(* Logix 5000 project; controller Test vendor 1 type 14 code 92 rev 33.11; software revision 33.00; part 2 of 2 *)

ADD_ON_INSTRUCTION Banner_QM30VT3_PD_FP_RMS_v5   (* revision 1.0 *)
VAR_IN_OUT
   Bytes : SINT[32]; {required}
   Data : Banner_QM30VT3_FP_RMS_PD_v5; {required}
END_VAR
VAR
   Temp : DINT[16]; {access None}
END_VAR

ROUTINE Logic   (* ladder *)
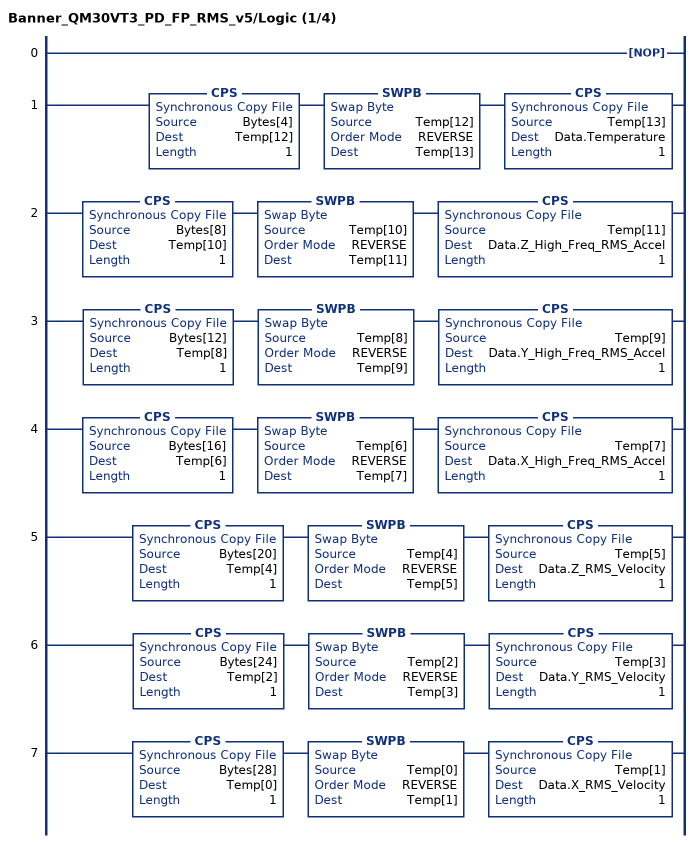
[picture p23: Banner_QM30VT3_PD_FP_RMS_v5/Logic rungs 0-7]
   0: NOP();
   1: CPS(Bytes[4],Temp[12],1)SWPB(Temp[12],REVERSE,Temp[13])CPS(Temp[13],Data.Temperature,1);
   2: CPS(Bytes[8],Temp[10],1)SWPB(Temp[10],REVERSE,Temp[11])CPS(Temp[11],Data.Z_High_Freq_RMS_Accel,1);
   3: CPS(Bytes[12],Temp[8],1)SWPB(Temp[8],REVERSE,Temp[9])CPS(Temp[9],Data.Y_High_Freq_RMS_Accel,1);
   4: CPS(Bytes[16],Temp[6],1)SWPB(Temp[6],REVERSE,Temp[7])CPS(Temp[7],Data.X_High_Freq_RMS_Accel,1);
   5: CPS(Bytes[20],Temp[4],1)SWPB(Temp[4],REVERSE,Temp[5])CPS(Temp[5],Data.Z_RMS_Velocity,1);
   6: CPS(Bytes[24],Temp[2],1)SWPB(Temp[2],REVERSE,Temp[3])CPS(Temp[3],Data.Y_RMS_Velocity,1);
   7: CPS(Bytes[28],Temp[0],1)SWPB(Temp[0],REVERSE,Temp[1])CPS(Temp[1],Data.X_RMS_Velocity,1);
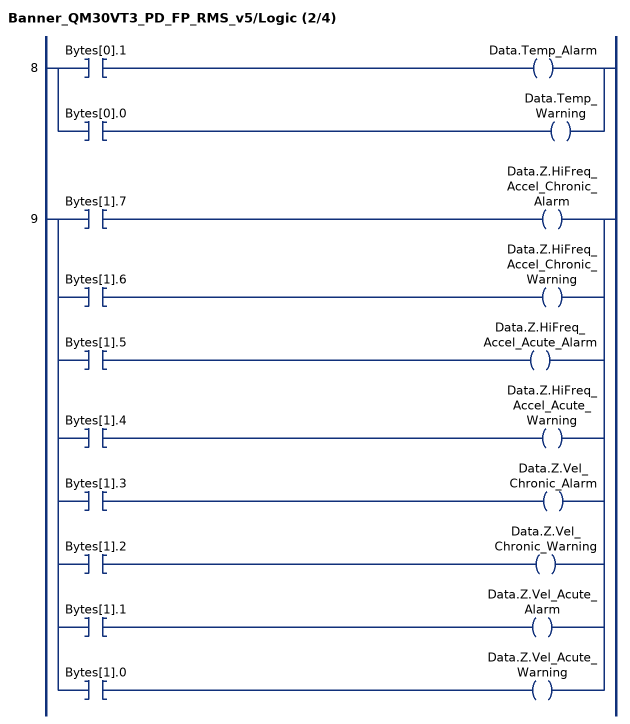
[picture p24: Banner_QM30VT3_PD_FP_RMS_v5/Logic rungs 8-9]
   8: [XIC(Bytes[0].1) OTE(Data.Temp_Alarm) ,XIC(Bytes[0].0) OTE(Data.Temp_Warning) ];
   9: [XIC(Bytes[1].7) OTE(Data.Z.HiFreq_Accel_Chronic_Alarm) ,XIC(Bytes[1].6) OTE(Data.Z.HiFreq_Accel_Chronic_Warning) ,XIC(Bytes[1].5) OTE(Data.Z.HiFreq_Accel_Acute_Alarm) ,XIC(Bytes[1].4) OTE(Data.Z.HiFreq_Accel_Acute_Warning) ,XIC(Bytes[1].3) OTE(Data.Z.Vel_Chronic_Alarm) ,XIC(Bytes[1].2) OTE(Data.Z.Vel_Chronic_Warning) ,XIC(Bytes[1].1) OTE(Data.Z.Vel_Acute_Alarm) ,XIC(Bytes[1].0) OTE(Data.Z.Vel_Acute_Warning) ];
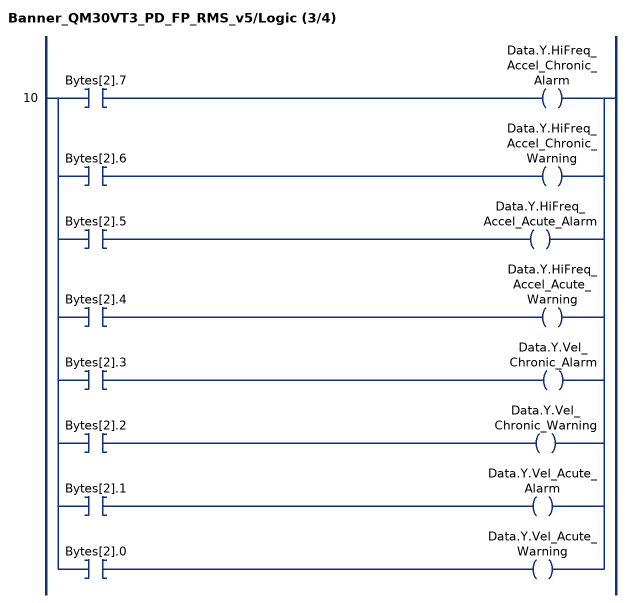
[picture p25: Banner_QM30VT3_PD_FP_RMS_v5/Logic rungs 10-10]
   10: [XIC(Bytes[2].7) OTE(Data.Y.HiFreq_Accel_Chronic_Alarm) ,XIC(Bytes[2].6) OTE(Data.Y.HiFreq_Accel_Chronic_Warning) ,XIC(Bytes[2].5) OTE(Data.Y.HiFreq_Accel_Acute_Alarm) ,XIC(Bytes[2].4) OTE(Data.Y.HiFreq_Accel_Acute_Warning) ,XIC(Bytes[2].3) OTE(Data.Y.Vel_Chronic_Alarm) ,XIC(Bytes[2].2) OTE(Data.Y.Vel_Chronic_Warning) ,XIC(Bytes[2].1) OTE(Data.Y.Vel_Acute_Alarm) ,XIC(Bytes[2].0) OTE(Data.Y.Vel_Acute_Warning) ];
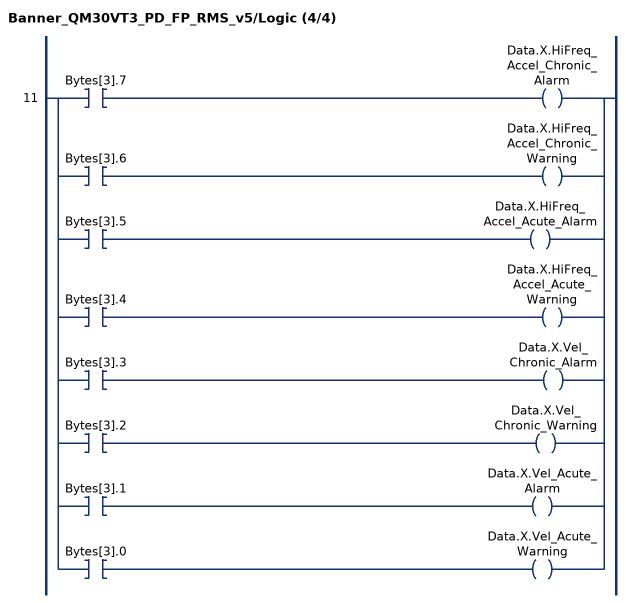
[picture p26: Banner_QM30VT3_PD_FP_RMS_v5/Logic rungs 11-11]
   11: [XIC(Bytes[3].7) OTE(Data.X.HiFreq_Accel_Chronic_Alarm) ,XIC(Bytes[3].6) OTE(Data.X.HiFreq_Accel_Chronic_Warning) ,XIC(Bytes[3].5) OTE(Data.X.HiFreq_Accel_Acute_Alarm) ,XIC(Bytes[3].4) OTE(Data.X.HiFreq_Accel_Acute_Warning) ,XIC(Bytes[3].3) OTE(Data.X.Vel_Chronic_Alarm) ,XIC(Bytes[3].2) OTE(Data.X.Vel_Chronic_Warning) ,XIC(Bytes[3].1) OTE(Data.X.Vel_Acute_Alarm) ,XIC(Bytes[3].0) OTE(Data.X.Vel_Acute_Warning) ];
END_ROUTINE
END_ADD_ON_INSTRUCTION

ADD_ON_INSTRUCTION Banner_QM30VT3_PD_SS_RMS_v5   (* revision 1.0 *)
VAR_IN_OUT
   Bytes : SINT[32]; {required}
   Data : Banner_QM30VT3_SS_RMS_PD_v5; {required}
END_VAR
VAR
   Temp : DINT[16]; {access None}
END_VAR

ROUTINE Logic   (* ladder *)
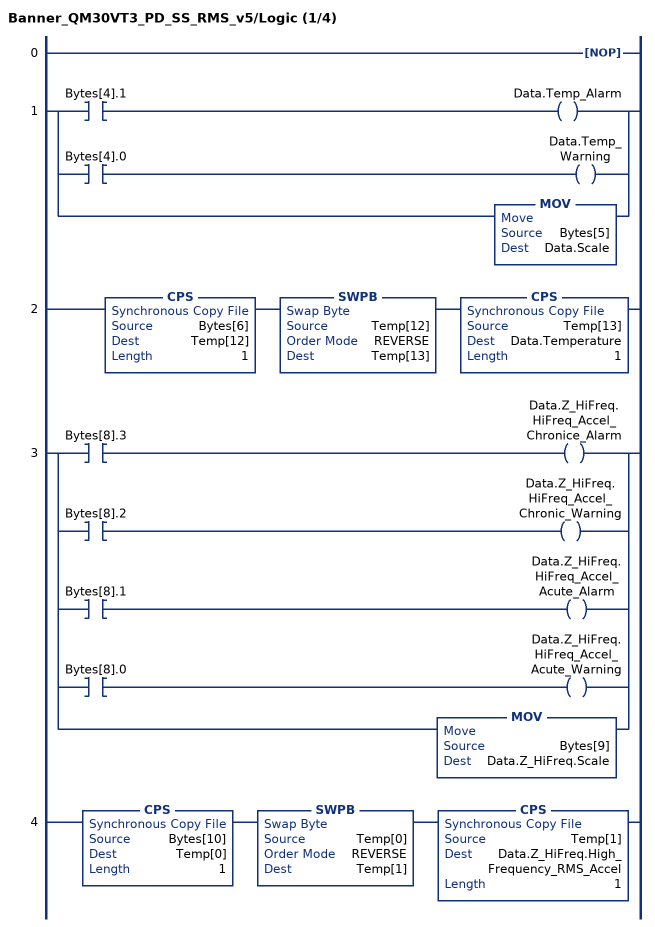
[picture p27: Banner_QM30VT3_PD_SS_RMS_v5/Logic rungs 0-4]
   0: NOP();
   1: [XIC(Bytes[4].1) OTE(Data.Temp_Alarm) ,XIC(Bytes[4].0) OTE(Data.Temp_Warning) ,MOV(Bytes[5],Data.Scale) ];
   2: CPS(Bytes[6],Temp[12],1)SWPB(Temp[12],REVERSE,Temp[13])CPS(Temp[13],Data.Temperature,1);
   3: [XIC(Bytes[8].3) OTE(Data.Z_HiFreq.HiFreq_Accel_Chronice_Alarm) ,XIC(Bytes[8].2) OTE(Data.Z_HiFreq.HiFreq_Accel_Chronic_Warning) ,XIC(Bytes[8].1) OTE(Data.Z_HiFreq.HiFreq_Accel_Acute_Alarm) ,XIC(Bytes[8].0) OTE(Data.Z_HiFreq.HiFreq_Accel_Acute_Warning) ,MOV(Bytes[9],Data.Z_HiFreq.Scale) ];
   4: CPS(Bytes[10],Temp[0],1)SWPB(Temp[0],REVERSE,Temp[1])CPS(Temp[1],Data.Z_HiFreq.High_Frequency_RMS_Accel,1);
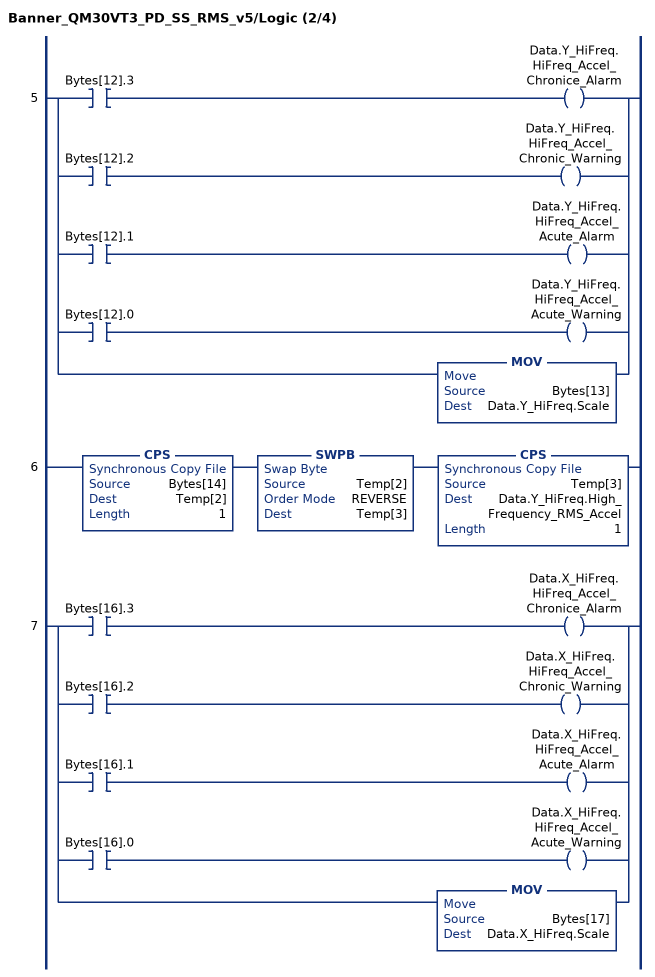
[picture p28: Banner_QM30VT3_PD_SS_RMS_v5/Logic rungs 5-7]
   5: [XIC(Bytes[12].3) OTE(Data.Y_HiFreq.HiFreq_Accel_Chronice_Alarm) ,XIC(Bytes[12].2) OTE(Data.Y_HiFreq.HiFreq_Accel_Chronic_Warning) ,XIC(Bytes[12].1) OTE(Data.Y_HiFreq.HiFreq_Accel_Acute_Alarm) ,XIC(Bytes[12].0) OTE(Data.Y_HiFreq.HiFreq_Accel_Acute_Warning) ,MOV(Bytes[13],Data.Y_HiFreq.Scale) ];
   6: CPS(Bytes[14],Temp[2],1)SWPB(Temp[2],REVERSE,Temp[3])CPS(Temp[3],Data.Y_HiFreq.High_Frequency_RMS_Accel,1);
   7: [XIC(Bytes[16].3) OTE(Data.X_HiFreq.HiFreq_Accel_Chronice_Alarm) ,XIC(Bytes[16].2) OTE(Data.X_HiFreq.HiFreq_Accel_Chronic_Warning) ,XIC(Bytes[16].1) OTE(Data.X_HiFreq.HiFreq_Accel_Acute_Alarm) ,XIC(Bytes[16].0) OTE(Data.X_HiFreq.HiFreq_Accel_Acute_Warning) ,MOV(Bytes[17],Data.X_HiFreq.Scale) ];
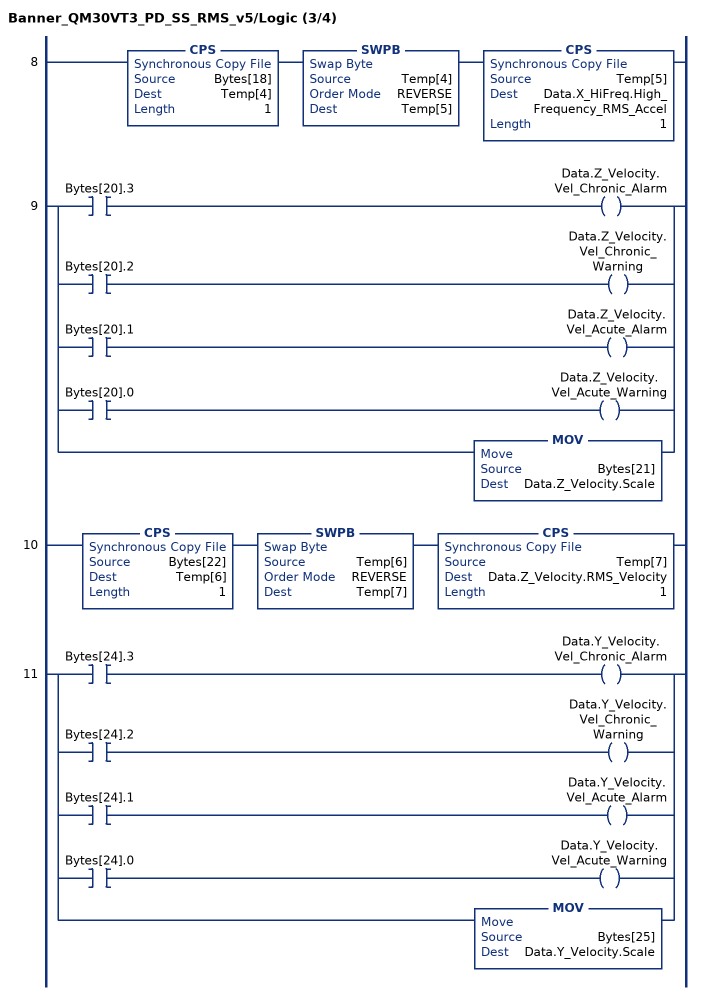
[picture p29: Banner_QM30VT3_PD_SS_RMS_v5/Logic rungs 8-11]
   8: CPS(Bytes[18],Temp[4],1)SWPB(Temp[4],REVERSE,Temp[5])CPS(Temp[5],Data.X_HiFreq.High_Frequency_RMS_Accel,1);
   9: [XIC(Bytes[20].3) OTE(Data.Z_Velocity.Vel_Chronic_Alarm) ,XIC(Bytes[20].2) OTE(Data.Z_Velocity.Vel_Chronic_Warning) ,XIC(Bytes[20].1) OTE(Data.Z_Velocity.Vel_Acute_Alarm) ,XIC(Bytes[20].0) OTE(Data.Z_Velocity.Vel_Acute_Warning) ,MOV(Bytes[21],Data.Z_Velocity.Scale) ];
   10: CPS(Bytes[22],Temp[6],1)SWPB(Temp[6],REVERSE,Temp[7])CPS(Temp[7],Data.Z_Velocity.RMS_Velocity,1);
   11: [XIC(Bytes[24].3) OTE(Data.Y_Velocity.Vel_Chronic_Alarm) ,XIC(Bytes[24].2) OTE(Data.Y_Velocity.Vel_Chronic_Warning) ,XIC(Bytes[24].1) OTE(Data.Y_Velocity.Vel_Acute_Alarm) ,XIC(Bytes[24].0) OTE(Data.Y_Velocity.Vel_Acute_Warning) ,MOV(Bytes[25],Data.Y_Velocity.Scale) ];
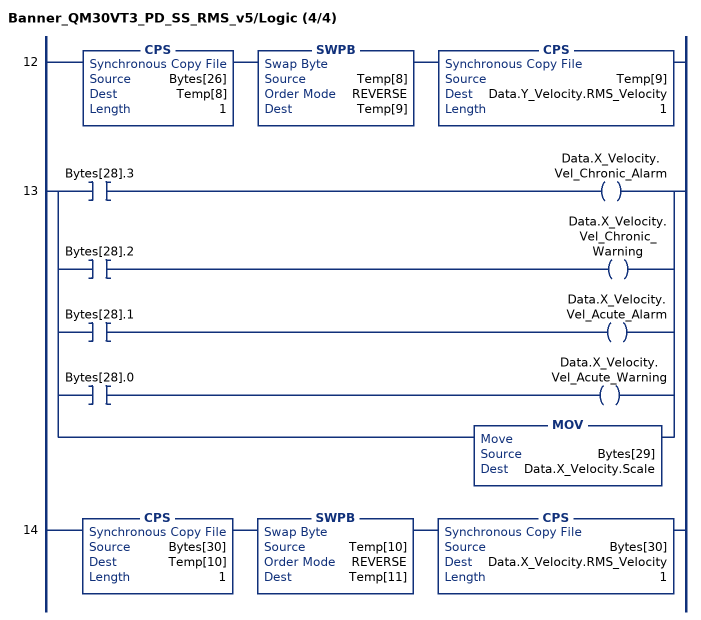
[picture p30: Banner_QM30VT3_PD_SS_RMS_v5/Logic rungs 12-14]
   12: CPS(Bytes[26],Temp[8],1)SWPB(Temp[8],REVERSE,Temp[9])CPS(Temp[9],Data.Y_Velocity.RMS_Velocity,1);
   13: [XIC(Bytes[28].3) OTE(Data.X_Velocity.Vel_Chronic_Alarm) ,XIC(Bytes[28].2) OTE(Data.X_Velocity.Vel_Chronic_Warning) ,XIC(Bytes[28].1) OTE(Data.X_Velocity.Vel_Acute_Alarm) ,XIC(Bytes[28].0) OTE(Data.X_Velocity.Vel_Acute_Warning) ,MOV(Bytes[29],Data.X_Velocity.Scale) ];
   14: CPS(Bytes[30],Temp[10],1)SWPB(Temp[10],REVERSE,Temp[11])CPS(Bytes[30],Data.X_Velocity.RMS_Velocity,1);
END_ROUTINE
END_ADD_ON_INSTRUCTION

ADD_ON_INSTRUCTION Banner_QM30VT3_PD_User_v5   (* revision 1.0 *)
VAR_IN_OUT
   Bytes : SINT[32]; {required}
   Data : Banner_QM30VT3_User_PD_v5; {required}
END_VAR
VAR
   Temp : DINT[16]; {access None}
END_VAR

ROUTINE Logic   (* ladder *)
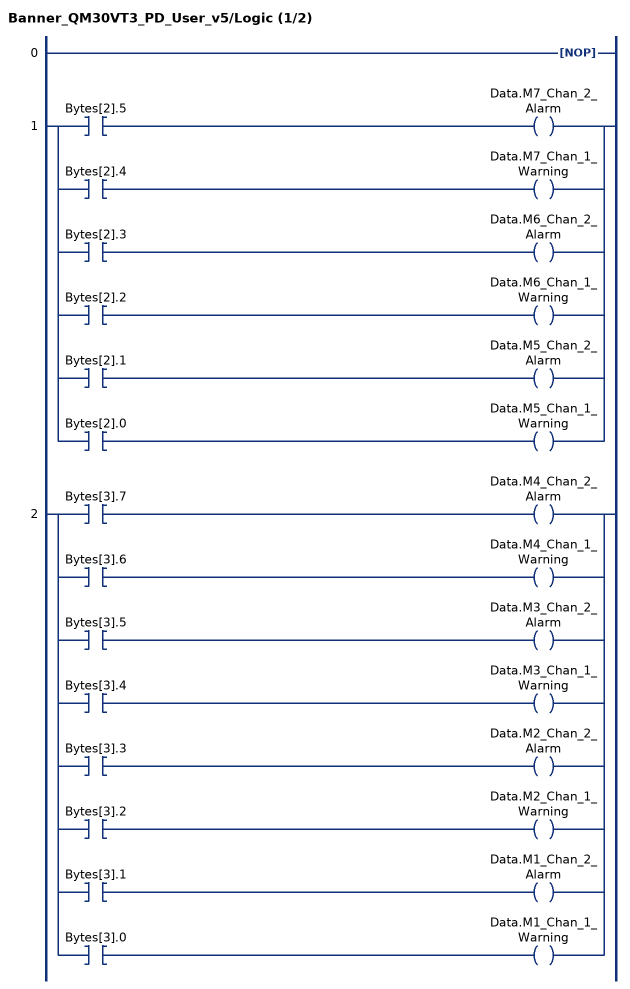
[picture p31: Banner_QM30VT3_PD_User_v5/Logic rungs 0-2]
   0: NOP();
   1: [XIC(Bytes[2].5) OTE(Data.M7_Chan_2_Alarm) ,XIC(Bytes[2].4) OTE(Data.M7_Chan_1_Warning) ,XIC(Bytes[2].3) OTE(Data.M6_Chan_2_Alarm) ,XIC(Bytes[2].2) OTE(Data.M6_Chan_1_Warning) ,XIC(Bytes[2].1) OTE(Data.M5_Chan_2_Alarm) ,XIC(Bytes[2].0) OTE(Data.M5_Chan_1_Warning) ];
   2: [XIC(Bytes[3].7) OTE(Data.M4_Chan_2_Alarm) ,XIC(Bytes[3].6) OTE(Data.M4_Chan_1_Warning) ,XIC(Bytes[3].5) OTE(Data.M3_Chan_2_Alarm) ,XIC(Bytes[3].4) OTE(Data.M3_Chan_1_Warning) ,XIC(Bytes[3].3) OTE(Data.M2_Chan_2_Alarm) ,XIC(Bytes[3].2) OTE(Data.M2_Chan_1_Warning) ,XIC(Bytes[3].1) OTE(Data.M1_Chan_2_Alarm) ,XIC(Bytes[3].0) OTE(Data.M1_Chan_1_Warning) ];
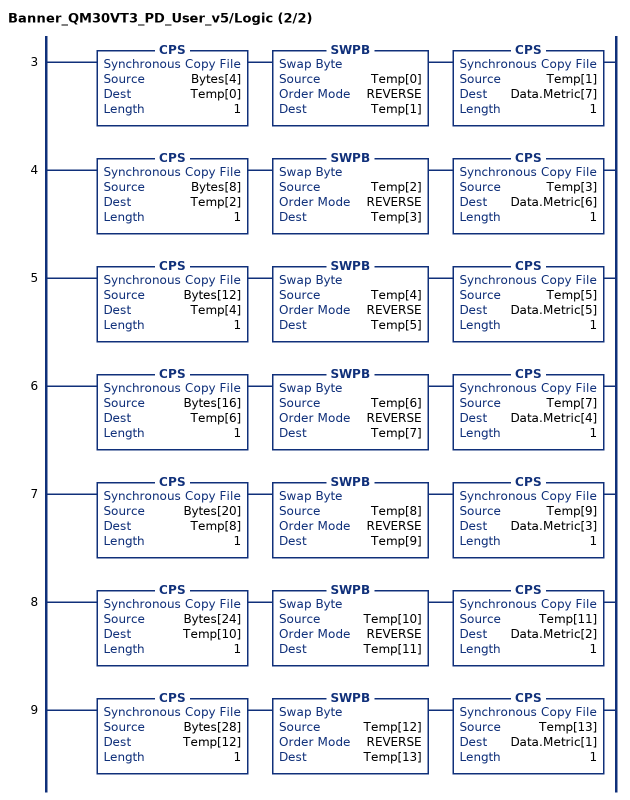
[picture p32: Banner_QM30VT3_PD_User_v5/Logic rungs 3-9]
   3: CPS(Bytes[4],Temp[0],1)SWPB(Temp[0],REVERSE,Temp[1])CPS(Temp[1],Data.Metric[7],1);
   4: CPS(Bytes[8],Temp[2],1)SWPB(Temp[2],REVERSE,Temp[3])CPS(Temp[3],Data.Metric[6],1);
   5: CPS(Bytes[12],Temp[4],1)SWPB(Temp[4],REVERSE,Temp[5])CPS(Temp[5],Data.Metric[5],1);
   6: CPS(Bytes[16],Temp[6],1)SWPB(Temp[6],REVERSE,Temp[7])CPS(Temp[7],Data.Metric[4],1);
   7: CPS(Bytes[20],Temp[8],1)SWPB(Temp[8],REVERSE,Temp[9])CPS(Temp[9],Data.Metric[3],1);
   8: CPS(Bytes[24],Temp[10],1)SWPB(Temp[10],REVERSE,Temp[11])CPS(Temp[11],Data.Metric[2],1);
   9: CPS(Bytes[28],Temp[12],1)SWPB(Temp[12],REVERSE,Temp[13])CPS(Temp[13],Data.Metric[1],1);
END_ROUTINE
END_ADD_ON_INSTRUCTION

ADD_ON_INSTRUCTION Banner_QM30VT3_PD_v5   (* revision 5.0 *)
VAR_IN_OUT
   QM30VT3 : Banner_QM30VT3_PDI_v5; {required}
END_VAR
VAR_INPUT
   Configuration : DINT; {required}
   Byte_Swap : BOOL; {required}
END_VAR
VAR
   Status_FP_RMS : Banner_QM30VT3_PD_FP_RMS_v5[2]; {access None}
   Status_SS_RMS : Banner_QM30VT3_PD_SS_RMS_v5[2]; {access None}
   Status_User : Banner_QM30VT3_PD_User_v5[2]; {access None}
END_VAR

ROUTINE Logic   (* ladder *)
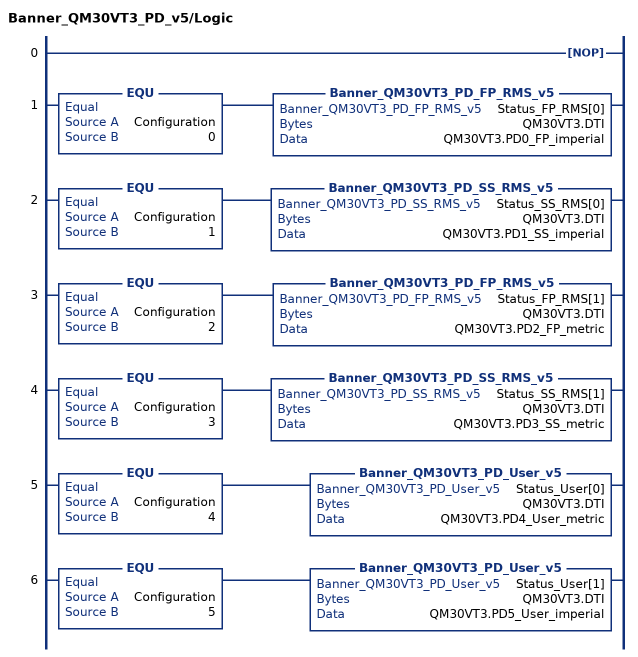
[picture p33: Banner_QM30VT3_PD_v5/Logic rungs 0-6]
   0: NOP();
   1: EQU(Configuration,0)Banner_QM30VT3_PD_FP_RMS_v5(Status_FP_RMS[0],QM30VT3.DTI,QM30VT3.PD0_FP_imperial);
   2: EQU(Configuration,1)Banner_QM30VT3_PD_SS_RMS_v5(Status_SS_RMS[0],QM30VT3.DTI,QM30VT3.PD1_SS_imperial);
   3: EQU(Configuration,2)Banner_QM30VT3_PD_FP_RMS_v5(Status_FP_RMS[1],QM30VT3.DTI,QM30VT3.PD2_FP_metric);
   4: EQU(Configuration,3)Banner_QM30VT3_PD_SS_RMS_v5(Status_SS_RMS[1],QM30VT3.DTI,QM30VT3.PD3_SS_metric);
   5: EQU(Configuration,4)Banner_QM30VT3_PD_User_v5(Status_User[0],QM30VT3.DTI,QM30VT3.PD4_User_metric);
   6: EQU(Configuration,5)Banner_QM30VT3_PD_User_v5(Status_User[1],QM30VT3.DTI,QM30VT3.PD5_User_imperial);
END_ROUTINE
END_ADD_ON_INSTRUCTION

VAR_GLOBAL   (* controller tags *)
   Bytes : SINT[4] := ([0] := 64, [1] := 73, [2] := 19, [3] := 57);
   IOLM1 : Banner_IOLM_v5;
   IOLM1_Status : Banner_DXMR_IOLM_Param_v5;
   Manual_Reset : BOOL;
   QM30VT3_IOLM1_01 : Banner_IOL_QM30VT3_Device;
        .Data.Index[4].Sub[10]   // SN10
        .Data.Index[4].Sub[5]   // SN5
        .Data.Index[4].Sub[11]   // SN11
        .Data.Metric_Config   // Index 9
        .Data.Index[2].Sub[5]   // IO-Link Version ID
        .Data.Index[4].Sub[1]   // SN1
        .Data.Index[2].Sub[6]   // Process Data Input Length
        .Data.Index[4].Sub[6]   // SN6
        .Data.Index[2].Sub[7]   // Process Data Output Length
        .Data.Index[2].Sub[3]   // Min Cycle Time
        .Data.Index[10]   // Status (ro)
        .Data.Index[4].Sub[7]   // SN7
        .Data.Index[2].Sub[2]   // Master Cycle Time
        .Data.Index[4].Sub[2]   // SN2
        .Data.Index[4].Sub[15]   // SN15
        .Data.Index[4].Sub[3]   // SN3
        .Data.Index[4].Sub[16]   // SN16
        .Data.Index[2].Sub[1]   // Reserved
        .Data.Index[3].Sub[1]   // Standard Command: 126=Locator Start, 127=Locator Stop, 129=Application Reset, 164=Reset All Metrics
        .Data.Index[10].Sub[1]   // Vibe IQ Status: 0=IDLE, 1=Start, 2=Samples Acquiring, 3=Processing, 4=Active
        .Data.Index[12].Sub[2]   // Velocity Threshold Compare: 0=Velocity Threshold or with Axis, 1=Velocity Threshold and with Axis
        .Data.Index[12].Sub[1]   // Start Baseline: 0=Idle, 1=Trigger Baseline, 2=Baseline Abord/Reset
        .Data.Index[12].Sub[4]   // Accel Velocity or and Threshold Exceed for Baseline: 0 to 65535
        .Data.Index[11].Sub[1]   // FMAx Settings: 1=Fmax 5300 Hz, 2=Fmax 2650 Hz, 3=Fmax 1300 Hz, 4=Fmax 650 Hz, 5=Fmax 325 Hz
        .Data.Index[4].Sub[8]   // SN8
        .Data.Index[2].Sub[4]   // M Sequence Capability
        .Data.Index[2].Sub[9]   // Device ID
        .Data.Index[4].Sub[9]   // SN9
        .Data.Index[4].Sub[12]   // SN12
        .Data.Index[4].Sub[13]   // SN13
        .Data.Index[4].Sub[14]   // SN14
        .Data.Index[4].Sub[4]   // SN4
        .Data.Index[2].Sub[8]   // Vendor ID
        .Data.Index[7]   // Process Data Mode
        .Data.Index[6]   // Resettable Run Time
        .Data.Index[4]   // Serial Number (ro)
        .Data.Index[3]   // Standard Command (wo)
        .Data.Index[5]   // All Time Run Time (ro)
        .Data.Index[5].Sub[1]   // All Time Run Time
        .Data.Index[6].Sub[1]   // Resettable Run Time
        .Data.Index[7].Sub[1]   // Process Data Mode: 0=FP Imperial, 1=SSP Imperial, 2=FP Metric, 3=SSP Metric, 4=FP User Define, 5=SSP User Define
        .Data.Index[8]   // Output Configuration
        .Data.Index[8].Sub[1]   // Wire Mode: 0=BannerBus, 1=Discrete Output
        .Data.Index[11]   // Vibe IQ Sampling
        .Data.Index[9].Sub[1]   // Metric 1
        .Data.Index[9]   // Reserved
        .Data.Index[9].Sub[2]   // Metric 1 Warning Threshold
        .Data.Index[9].Sub[3]   // Metric 1 Alarm Threshold
        .Data.Index[9].Sub[4]   // Metric 2
        .Data.Index[9].Sub[5]   // Metric 2 Warning Threshold
        .Data.Index[9].Sub[6]   // Metric 2 Alarm Threshold
        .Data.Index[9].Sub[7]   // Metric 3
        .Data.Index[9].Sub[8]   // Metric 3 Warning Threshold
        .Data.Index[9].Sub[9]   // Metric 3 Alarm Threshold
        .Data.Index[9].Sub[10]   // Metric 4
        .Data.Index[9].Sub[11]   // Metric 4 Warning Threshold
        .Data.Index[9].Sub[12]   // Metric Alarm Threshold
        .Data.Index[9].Sub[13]   // Metric 5
        .Data.Index[9].Sub[14]   // Metric 5 Warning Threshold
        .Data.Index[9].Sub[15]   // Metric 5 Alarm Threshold
        .Data.Index[9].Sub[16]   // Metric 6
        .Data.Index[9].Sub[17]   // Metric 6 Warning Threshold
        .Data.Index[9].Sub[18]   // Metric 6 Alarm Threshold
        .Data.Index[9].Sub[19]   // Metric 7 Alarm Threshold
        .Data.Index[9].Sub[20]   // Metric 7 Warning Threshold
        .Data.Index[9].Sub[21]   // Metric 7 Alarm Threshold
        .Data.Index[9].Sub[22]   // Number of Threshold Samples
        .Data.Index[12]   // Baseline Configuration
        .Data.Index[10].Sub[2]   // Baseline Sample Left
        .Data.Index[13]   // Baseline Threshold Configuration
        .Data.Index[14]   // Baseline Avg Configuration
        .Data.Index[12].Sub[9]   // Imperial or Metric Selection: 0=Imperial, 1=Metric
        .Data.Index[15]   // Baseline Warning Threshold Configuration
        .Data.Index[16]   // Baseline Alarm Threshold Configuration
        .Data.Index[17]   // Baseline Temp Alarm Warning Threshold
        .Data.Index[2]   // Direct Parameters 1 (ro)
        .Data.Index[12].Sub[3]   // Accel Component for Threshold: 0 to 65535
        .Data.Index[12].Sub[5]   // Number of Samples for Baseline: 0 to 65535
        .Data.Index[12].Sub[6]   // Sample Rate in seconds for Baseline: 0 to 65535
        .Data.Index[12].Sub[7]   // Number of Samples for Acute: 0 to 65535
        .Data.Index[12].Sub[8]   // Number of Samples for Chronic: 0 to 65535
        .Data.Index[13].Sub[1]   // X RMS Velocity Threshold for Baseline: 0 to 65535
        .Data.Index[13].Sub[2]   // Y RMS Velocity Threshold for Baseline: 0 to 65535
        .Data.Index[13].Sub[3]   // Z RMS Velocity Threshold for Baseline: 0 to 65535
        .Data.Index[13].Sub[4]   // X RMS HP Accel Threshold for Baseline: 0 to 65535
        .Data.Index[13].Sub[5]   // Y RMS HP Accel Threshold for Baseline: 0 to 65535
        .Data.Index[13].Sub[6]   // Z RMS HP Accel Threshold for Baseline: 0 to 65535
        .Data.Index[14].Sub[1]   // X RMS Velocity Vib Baseline: 0 to 65535
        .Data.Index[14].Sub[2]   // Y RMS Velocity Vib Baseline: 0 to 65535
        .Data.Index[14].Sub[3]   // Z RMS Velocity Vib Baseline: 0 to 65535
        .Data.Index[14].Sub[4]   // X RMS HP Accel Vibration Baseline: 0 to 65535
        .Data.Index[14].Sub[5]   // Y RMS HP Accel Vibration Baseline: 0 to 65535
        .Data.Index[14].Sub[6]   // Z RMS HP Accel Vibration Baseline: 0 to 65535
        .Data.Index[15].Sub[1]   // X RMS Velocity Warning Threshold: 0 to 65535
        .Data.Index[15].Sub[2]   // Y RMS Velocity Warning Threshold: 0 to 65535
        .Data.Index[15].Sub[3]   // Z RMS Velocity Warning Threshold: 0 to 65535
        .Data.Index[15].Sub[4]   // X RMS HP Accel Warning Threshold: 0 to 65535
        .Data.Index[15].Sub[5]   // Y RMS HP Accel Warning Threshold: 0 to 65535
        .Data.Index[15].Sub[6]   // Z RMS HP Accel Warning Threshold: 0 to 65535
        .Data.Index[16].Sub[1]   // X RMS Velocity Alarm Threshold: 0 to 65535
        .Data.Index[16].Sub[2]   // Y RMS Velocity Alarm Threshold: 0 to 65535
        .Data.Index[16].Sub[3]   // Z RMS Velocity Alarm Threshold: 0 to 65535
        .Data.Index[16].Sub[4]   // X RMS HP Accel Alarm Threshold: 0 to 65535
        .Data.Index[16].Sub[5]   // Y RMS HP Accel Alarm Threshold: 0 to 65535
        .Data.Index[16].Sub[6]   // Z RMS HP Accel Alarm Threshold: 0 to 65535
        .Data.Index[17].Sub[1]   // Temp Warning Treshold Value: 0 to 65535
        .Data.Index[17].Sub[2]   // Temp Alarm Threshold Value: 0 to 65535
   QM30VT3_IOLM1_01_PD : Banner_QM30VT3_PDI_v5;
   QM30VT3_IOLM1_01_PD_Status : Banner_QM30VT3_PD_v5;
   QM30VT3_Rules : Banner_IOL_Rules_Array;
        .Settings[10]   // Status
        .Settings[8]   // Output Configuration
        .Settings[4]   // Serial Number
        .Settings[15].Rules[1]   // Y RMS Velocity Warning Threshold
        .Settings[4].Rules[0]   // SN1
        .Settings[16]   // Baseline Alarm Threshold Configuration
        .Settings[10].Rules[1]   // Baseline Sample Left
        .Settings[12].Rules[4]   // Number of Samples for Baseline
        .Settings[12].Rules[6]   // Number of Samples for Acute
        .Settings[12].Rules[7]   // Number of Samples for Chronic
        .Settings[9]   // Metric Configuration
        .Settings[2].Rules[8]   // Device ID
        .Settings[4].Rules[6]   // SN7
        .Settings[4].Rules[7]   // SN8
        .Settings[2].Rules[4]   // IO-Link ID
        .Settings[13].Rules[0]   // X RMS Velocity Threshold for Baseline
        .Settings[14].Rules[0]   // X RMS Velocity Baseline Value
        .Settings[9].Rules[2]   // Metric 1 Alarm Threshold
        .Settings[14].Rules[5]   // Z RMS HP Accel Baseline Value
        .Settings[3]   // Standard Command
        .Settings[17]   // Baseline Temp Alarm Warning Threshold
        .Settings[4].Rules[1]   // SN2
        .Settings[4].Rules[2]   // SN3
        .Settings[4].Rules[15]   // SN16
        .Settings[4].Rules[14]   // SN15
        .Settings[4].Rules[10]   // SN11
        .Settings[4].Rules[11]   // SN12
        .Settings[13]   // Baseline Threshold Configuration
        .Settings[3].Rules[0]   // Standard Command
        .Settings[7].Rules[0]   // Process Data Mode
        .Settings[2].Rules[1]   // Master Cycle Time
        .Settings[12].Rules[8]   // Imperial or Metric Selection
        .Settings[8].Rules[0]   // Output Configuration
        .Settings[2].Rules[2]   // Min Cycle Time
        .Settings[5]   // All Time Run Time
        .Settings[15]   // Baseline Warning Threhsold Configuration
        .Settings[5].Rules[0]   // All Time Run Time
        .Settings[4].Rules[8]   // SN9
        .Settings[15].Rules[0]   // X RMS Velocity Warning Threshold
        .Settings[6]   // Resettable Run Time
        .Settings[2].Rules[0]   // Reserved
        .Settings[4].Rules[12]   // SN13
        .Settings[15].Rules[2]   // Z RMS Velocity Warning Threshold
        .Settings[16].Rules[2]   // Z RMS Velocity Alarm Threshold
        .Settings[15].Rules[3]   // X RMS HP Accel Warning Threshold
        .Settings[4].Rules[13]   // SN14
        .Settings[15].Rules[4]   // Y RMS HP Accel Warning Threshold
        .Settings[16].Rules[0]   // X RMS Velocity Alarm Threshold
        .Settings[16].Rules[3]   // X RMS HP Accel Alarm Threshold
        .Settings[15].Rules[5]   // Z RMS HP Accel Warning Threshold
        .Settings[7]   // Process Data Mode
        .Settings[9].Rules[16]   // Metric 6 Warning Threshold
        .Settings[9].Rules[3]   // Metric 2
        .Settings[11]   // Vibe IQ Sampling
        .Settings[4].Rules[3]   // SN4
        .Settings[4].Rules[4]   // SN5
        .Settings[4].Rules[5]   // SN6
        .Settings[14].Rules[4]   // Y RMS HP Accel Baseline Value
        .Settings[2]   // Direct Parameters 1
        .Settings[2].Rules[7]   // Vendor ID
        .Settings[16].Rules[1]   // Y RMS Velocity Alarm Threshold
        .Settings[16].Rules[4]   // Y RMS HP Accel Alarm Threshold
        .Settings[12]   // Baseline Configuration
        .Settings[12].Rules[3]   // Accel Velocity or and Threshold Exceed for Baseline
        .Settings[12].Rules[5]   // Sample Rate in seconds for Baseline
        .Settings[9].Rules[4]   // Metric 2 Warning Threshold
        .Settings[9].Rules[5]   // Metric 2 Alarm Threshold
        .Settings[9].Rules[17]   // Metric 6 Alarm Threshold
        .Settings[2].Rules[5]   // Process Data Input Length
        .Settings[13].Rules[1]   // Y RMS Velocity Threshold for Baseline
        .Settings[12].Rules[1]   // Velocity Threshold Compare
        .Settings[9].Rules[6]   // Metric 3
        .Settings[9].Rules[7]   // Metric 3 Warning Threshold
        .Settings[9].Rules[18]   // Metric 7
        .Settings[2].Rules[3]   // M-Sequence Capability
        .Settings[13].Rules[2]   // Z RMS Velocity Threshold for Baseline
        .Settings[14].Rules[1]   // Y RMS Velocity Baseline Value
        .Settings[9].Rules[8]   // Metric 3 Alarm Threshold
        .Settings[9].Rules[9]   // Metric 4
        .Settings[9].Rules[19]   // Metric 7 Warning Threshold
        .Settings[2].Rules[6]   // Process Data Output Length
        .Settings[6].Rules[0]   // Resettable Run Time
        .Settings[13].Rules[3]   // X RMS HP Accel Threshold for Baseline
        .Settings[12].Rules[2]   // Accel Component for Threshold
        .Settings[9].Rules[10]   // Metric 4 Warning Threshold
        .Settings[9].Rules[11]   // Metric 4 Alarm Threshold
        .Settings[9].Rules[20]   // Metric 7 Alarm Threshold
        .Settings[9].Rules[0]   // Metric 1
        .Settings[13].Rules[4]   // Y RMS HP Accel Threshold for Baseline
        .Settings[14].Rules[2]   // Z RMS Velocity Baseline Value
        .Settings[9].Rules[12]   // Metric 5
        .Settings[9].Rules[13]   // Metric 5 Warning Threshold
        .Settings[9].Rules[21]   // Number of Threshold Samples
        .Settings[11].Rules[0]   // FMax Settings
        .Settings[9].Rules[1]   // Metric 1 Warning Threshold
        .Settings[4].Rules[9]   // SN10
        .Settings[14]   // Baseline Avg Configuration
        .Settings[12].Rules[0]   // Start Baseline
        .Settings[13].Rules[5]   // Z RMS HP Accel Threshold for Baseline
        .Settings[14].Rules[3]   // X RMS HP Accel Baseline Value
        .Settings[9].Rules[14]   // Metric 5 Alarm Threshold
        .Settings[9].Rules[15]   // Metric 6
        .Settings[10].Rules[0]   // Vibe IQ Status
        .Settings[16].Rules[5]   // Z RMS HP Accel Alarm Threshold
        .Settings[17].Rules[0]   // Temp Warning Threshold Value
        .Settings[17].Rules[1]   // Temp Alarm Threshold Value
   QM30VT_IOLM1_01_Status : Banner_IOL_QM30VT3_Parameter_v5;
   Update : BOOL;
END_VAR

PROGRAM MainProgram   (* main routine MainRoutine *)

ROUTINE MainRoutine   (* ladder *)
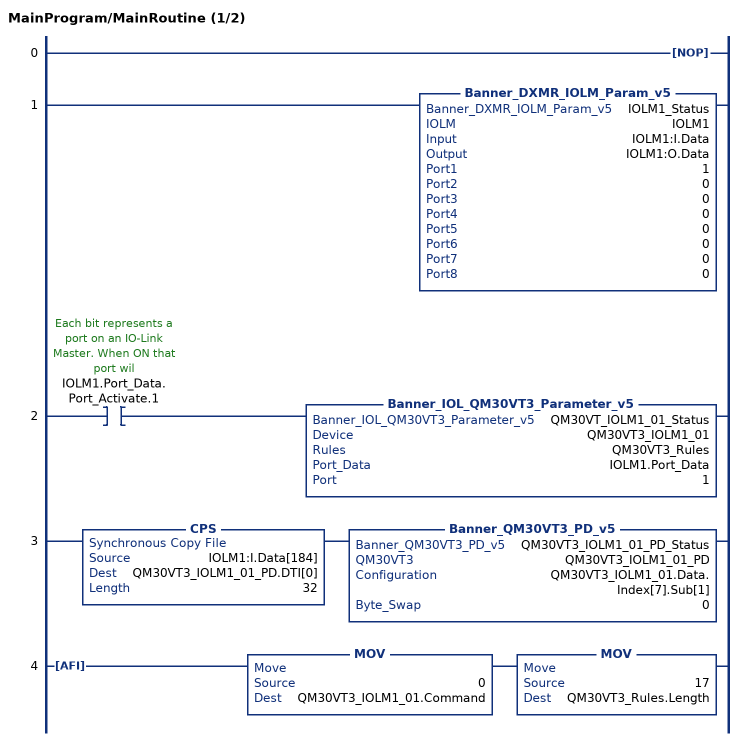
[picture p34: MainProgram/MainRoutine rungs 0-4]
   0: NOP();
   1: Banner_DXMR_IOLM_Param_v5(IOLM1_Status,IOLM1,IOLM1:I.Data,IOLM1:O.Data,1,0,0,0,0,0,0,0);
   2: XIC(IOLM1.Port_Data.Port_Activate.1)Banner_IOL_QM30VT3_Parameter_v5(QM30VT_IOLM1_01_Status,QM30VT3_IOLM1_01,QM30VT3_Rules,IOLM1.Port_Data,1);
   3: CPS(IOLM1:I.Data[184],QM30VT3_IOLM1_01_PD.DTI[0],32)Banner_QM30VT3_PD_v5(QM30VT3_IOLM1_01_PD_Status,QM30VT3_IOLM1_01_PD,QM30VT3_IOLM1_01.Data.Index[7].Sub[1],0);
   4: AFI()MOV(0,QM30VT3_IOLM1_01.Command)MOV(17,QM30VT3_Rules.Length);
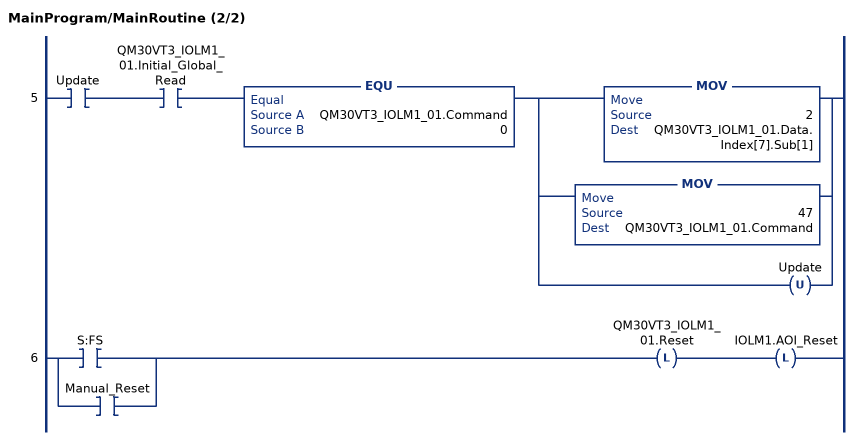
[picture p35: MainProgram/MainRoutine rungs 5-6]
   5: XIC(Update)XIC(QM30VT3_IOLM1_01.Initial_Global_Read)EQU(QM30VT3_IOLM1_01.Command,0)[MOV(2,QM30VT3_IOLM1_01.Data.Index[7].Sub[1]) ,MOV(47,QM30VT3_IOLM1_01.Command) ,OTU(Update) ];
   6: [XIC(S:FS) ,XIC(Manual_Reset) ]OTL(QM30VT3_IOLM1_01.Reset)OTL(IOLM1.AOI_Reset);
END_ROUTINE
END_PROGRAM
